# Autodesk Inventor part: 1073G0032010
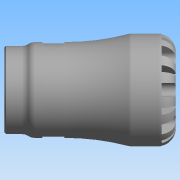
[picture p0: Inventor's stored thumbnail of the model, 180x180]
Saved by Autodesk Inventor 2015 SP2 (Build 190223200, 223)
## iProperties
Created: 2016-12
Part Number: 1073G0032010
Material: Generic
Description: PLASSON FEMALE INTEGRAL BRASS THREAD 32X1" G SERIES 1
Document SubType Name: Modeling
Designer: KIM
Density: 1 g/cm^3
Appearance: Default
Author: KIM
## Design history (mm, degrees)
derived "1073G.ipt"
feature "Solid1::1073G.ipt"
tag "TaggingFeature1"
body "Solid1"
other parameters: "d0" = 88, "d1" = 23.52, "d2" = 32, "d4" = 58, "d6" = 56, "d8" = 49.3, "d13" = 7.2, "d14" = 7.2, "d15" = 0, "d17" = 360 deg, "d19" = 8 deg, "d20" = 0.64, "d21" = 0.64, "d22" = 8 deg, "d24" = 0, "d26" = 360 deg, "d32" = 5.8, "d33" = 5.8, "d39" = 0.90873, "d42" = 30.291, "d43" = 45.24, "d46" = 2.66667, "d47" = 13.5, "d48" = 28.77645, "d50" = 6.105, "d51" = 0.58, "d54" = 11.2, "d55" = 7.04, "d57" = 14.112, "d58" = 0, "d68" = 360 deg, "d72" = 0.64, "d74" = 0, "d76" = 9.52, "d_" = 32, "E_" = 58, "H_" = 88, "l_" = 56, "G_" = 30.291, "l_2" = 13.5, "d9" = 9, "d11" = 58, "d49" = 18.5
